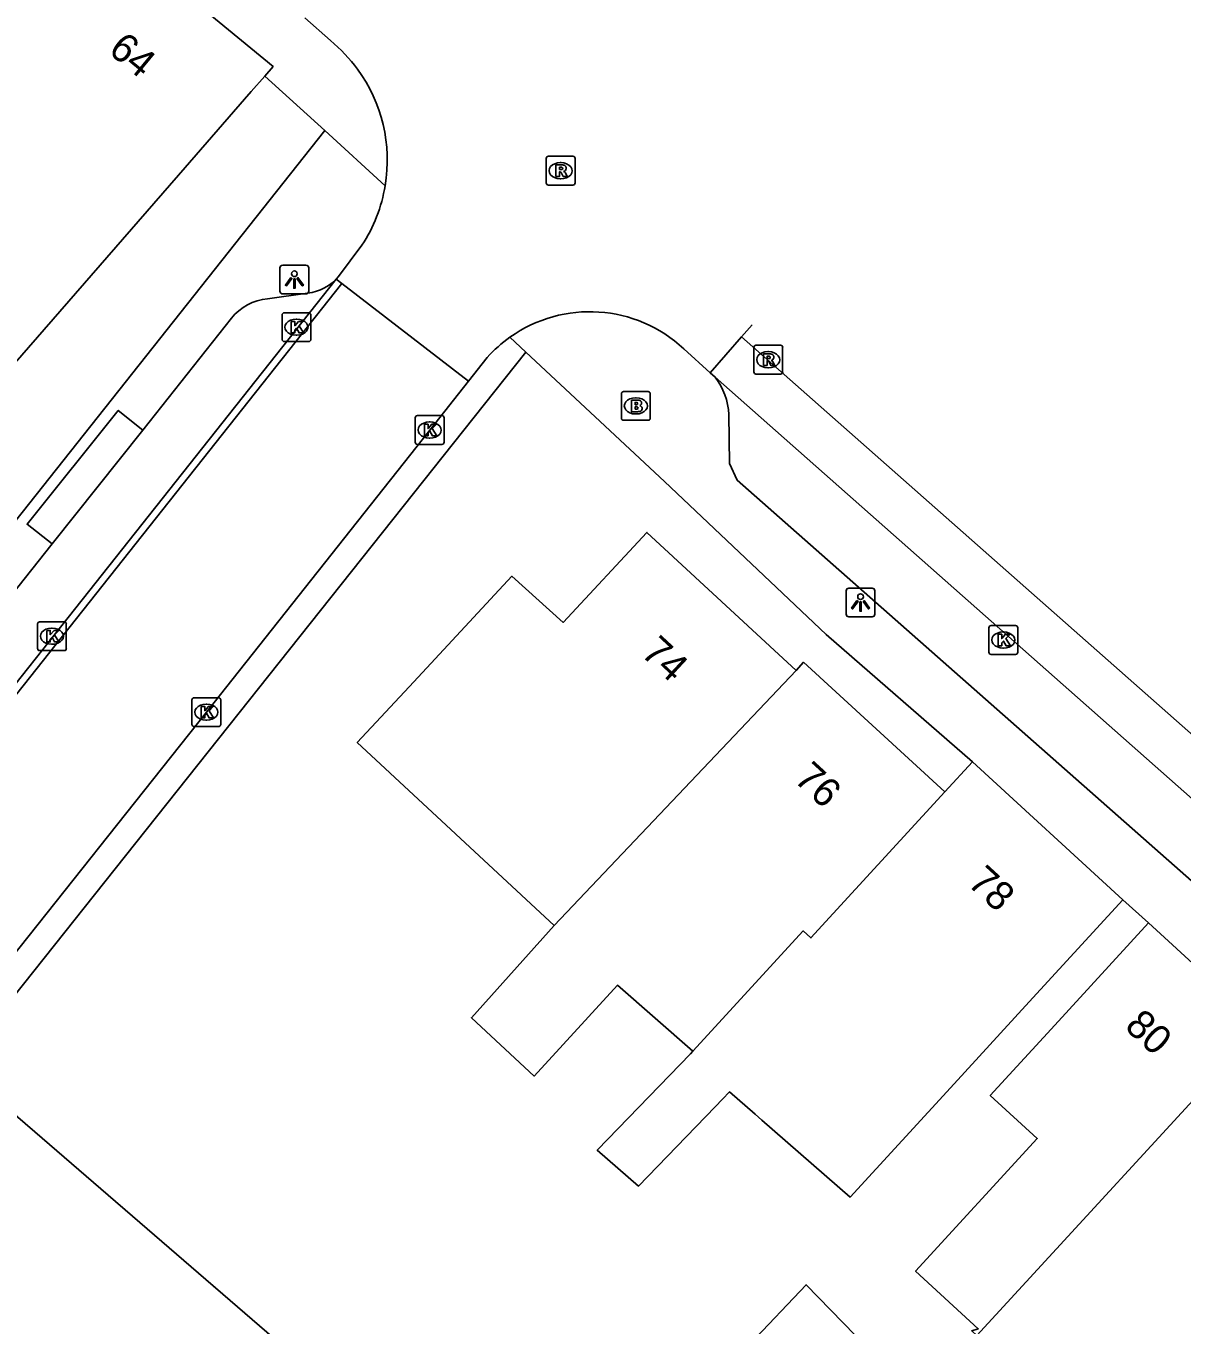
# Model space of a CAD drawing. Extents: x 161882 to 162509, y 381687 to 382379.
# Drawn here: x 162098.84 to 162138.96, y 382136.14 to 382181.25 of the extents above; entities that cross this region are included whole.
import ezdxf

# ---------------------------------------------------------------- set-up
doc = ezdxf.new("R2010")
doc.units = 0
for name, color, linetype in [('IMGEO_Brandkraan', 7, 'Continuous'), ('IMGEO_Kolk', 7, 'Continuous'), ('IMGEO_Lichtpunt', 7, 'Continuous'), ('IMGEO_Pand', 7, 'Continuous'), ('IMGEO_Pand_nummerreeks', 7, 'Continuous'), ('IMGEO_Rijbaan_lokaal_gesloten', 7, 'Continuous'), ('IMGEO_Rijbaan_lokaal_open', 7, 'Continuous'), ('IMGEO_Rioolput', 7, 'Continuous'), ('IMGEO_Voetpad_gesloten', 7, 'Continuous'), ('IMGEO_Voetpad_open', 7, 'Continuous')]:
    doc.layers.add(name, color=color, linetype=linetype)

msp = doc.modelspace()

# ---------------------------------------------------------------- linework, layer by layer
at = {"layer": 'IMGEO_Brandkraan'}
for p, q in [((162119.509, 382167.63), (162119.509, 382168.482)), ((162119.584, 382168.556), (162120.436, 382168.556)), ((162119.997, 382168.336), (162120.022, 382168.336)), ((162120.51, 382168.482), (162120.51, 382167.63)), ((162120.436, 382167.556), (162119.584, 382167.556)), ((162120.02, 382167.776), (162119.995, 382167.776))]:
    msp.add_line(p, q, dxfattribs=at)
for points in [[(162119.509, 382167.63), (162119.509, 382168.482)], [(162119.584, 382168.556), (162120.436, 382168.556)], [(162120.51, 382168.482), (162120.51, 382167.63)], [(162119.857, 382168.256), (162119.857, 382167.856), (162120.07, 382167.856)], [(162120.088, 382168.256), (162119.857, 382168.256)], [(162120.036, 382168.175), (162119.982, 382168.175), (162119.982, 382168.099)], [(162119.982, 382168.099), (162120.035, 382168.099)], [(162120.044, 382168.023), (162119.982, 382168.023), (162119.982, 382167.942)], [(162119.982, 382167.942), (162120.044, 382167.942)], [(162120.436, 382167.556), (162119.584, 382167.556)]]:
    msp.add_lwpolyline(points, dxfattribs=at)
for centre, radius, start, end in [((162119.586, 382168.48), 0.0765, 91.552, 178.448), ((162119.586, 382168.48), 0.0765, 91.552, 178.448), ((162120.434, 382168.48), 0.0765, 1.552, 88.448), ((162120.434, 382168.48), 0.0765, 1.552, 88.448), ((162120.037, 382168.137), 0.0379, 267.8285, 90.9355), ((162120.045, 382167.982), 0.0404, 269.8759, 90.5077), ((162120.076, 382168.107), 0.251, 268.6676, 293.5347), ((162120.092, 382168.111), 0.145, 59.4692, 91.5367), ((162120.117, 382168.158), 0.0922, 285.5137, 58.1501), ((162120.122, 382167.966), 0.105, 301.3115, 78.989), ((162119.586, 382167.632), 0.0765, 181.552, 268.448), ((162119.586, 382167.632), 0.0765, 181.552, 268.448), ((162120.434, 382167.632), 0.0765, 271.552, 358.448), ((162120.434, 382167.632), 0.0765, 271.552, 358.448)]:
    msp.add_arc(centre, radius, start, end, dxfattribs=at)
for centre, major_axis, ratio, start_param, end_param in [((162119.996, 382168.056), (-0.387, 0.002), 0.722429, 4.712389, 7.853982), ((162120.021, 382168.056), (-0.39, 0.002), 0.717154, 1.570796, 4.712389)]:
    msp.add_ellipse(centre, major_axis=major_axis, ratio=ratio, start_param=start_param, end_param=end_param, dxfattribs=at)
at = {"layer": 'IMGEO_Kolk'}
for p, q in [((162107.729, 382170.365), (162107.729, 382171.217)), ((162107.804, 382171.291), (162108.656, 382171.291)), ((162108.217, 382171.071), (162108.242, 382171.071)), ((162108.73, 382171.217), (162108.73, 382170.365)), ((162108.656, 382170.291), (162107.804, 382170.291)), ((162108.24, 382170.511), (162108.215, 382170.511)), ((162112.353, 382166.793), (162112.353, 382167.645)), ((162112.428, 382167.719), (162113.28, 382167.719)), ((162112.841, 382167.499), (162112.866, 382167.499)), ((162113.354, 382167.645), (162113.354, 382166.793)), ((162112.864, 382166.939), (162112.839, 382166.939)), ((162113.28, 382166.719), (162112.428, 382166.719)), ((162099.242, 382159.632), (162099.242, 382160.484)), ((162099.317, 382160.558), (162100.169, 382160.558)), ((162099.73, 382160.338), (162099.755, 382160.338)), ((162100.243, 382160.484), (162100.243, 382159.632)), ((162132.263, 382159.501), (162132.263, 382160.353)), ((162132.338, 382160.427), (162133.19, 382160.427)), ((162132.751, 382160.207), (162132.776, 382160.207)), ((162133.264, 382160.353), (162133.264, 382159.501)), ((162099.753, 382159.778), (162099.728, 382159.778)), ((162100.169, 382159.558), (162099.317, 382159.558)), ((162133.19, 382159.427), (162132.338, 382159.427)), ((162132.774, 382159.647), (162132.749, 382159.647)), ((162104.678, 382157.923), (162105.53, 382157.923)), ((162104.603, 382156.997), (162104.603, 382157.849)), ((162105.091, 382157.703), (162105.116, 382157.703)), ((162105.604, 382157.849), (162105.604, 382156.997)), ((162105.114, 382157.143), (162105.089, 382157.143)), ((162105.53, 382156.923), (162104.678, 382156.923))]:
    msp.add_line(p, q, dxfattribs=at)
for points in [[(162107.729, 382170.365), (162107.729, 382171.217)], [(162107.804, 382171.291), (162108.656, 382171.291)], [(162108.05, 382170.991), (162108.173, 382170.991), (162108.173, 382170.84), (162108.303, 382170.991), (162108.467, 382170.991), (162108.321, 382170.84), (162108.474, 382170.591), (162108.322, 382170.591), (162108.237, 382170.755), (162108.173, 382170.688), (162108.173, 382170.591), (162108.05, 382170.591), (162108.05, 382170.991)], [(162108.73, 382171.217), (162108.73, 382170.365)], [(162108.656, 382170.291), (162107.804, 382170.291)], [(162112.353, 382166.793), (162112.353, 382167.645)], [(162112.428, 382167.719), (162113.28, 382167.719)], [(162112.674, 382167.419), (162112.797, 382167.419), (162112.797, 382167.268), (162112.927, 382167.419), (162113.091, 382167.419), (162112.945, 382167.268), (162113.098, 382167.019), (162112.946, 382167.019), (162112.861, 382167.183), (162112.797, 382167.116), (162112.797, 382167.019), (162112.674, 382167.019), (162112.674, 382167.419)], [(162113.354, 382167.645), (162113.354, 382166.793)], [(162113.28, 382166.719), (162112.428, 382166.719)], [(162099.242, 382159.632), (162099.242, 382160.484)], [(162099.317, 382160.558), (162100.169, 382160.558)], [(162099.563, 382160.258), (162099.686, 382160.258), (162099.686, 382160.107), (162099.816, 382160.258), (162099.98, 382160.258), (162099.834, 382160.107), (162099.987, 382159.858), (162099.835, 382159.858), (162099.75, 382160.022), (162099.686, 382159.955), (162099.686, 382159.858), (162099.563, 382159.858), (162099.563, 382160.258)], [(162100.243, 382160.484), (162100.243, 382159.632)], [(162132.263, 382159.501), (162132.263, 382160.353)], [(162132.338, 382160.427), (162133.19, 382160.427)], [(162133.264, 382160.353), (162133.264, 382159.501)], [(162132.584, 382160.127), (162132.707, 382160.127), (162132.707, 382159.976), (162132.837, 382160.127), (162133.001, 382160.127), (162132.855, 382159.976), (162133.008, 382159.727), (162132.856, 382159.727), (162132.771, 382159.891), (162132.707, 382159.824), (162132.707, 382159.727), (162132.584, 382159.727), (162132.584, 382160.127)], [(162100.169, 382159.558), (162099.317, 382159.558)], [(162133.19, 382159.427), (162132.338, 382159.427)], [(162104.678, 382157.923), (162105.53, 382157.923)], [(162104.603, 382156.997), (162104.603, 382157.849)], [(162104.924, 382157.623), (162105.047, 382157.623), (162105.047, 382157.472), (162105.177, 382157.623), (162105.341, 382157.623), (162105.195, 382157.472), (162105.348, 382157.223), (162105.196, 382157.223), (162105.111, 382157.387), (162105.047, 382157.32), (162105.047, 382157.223), (162104.924, 382157.223), (162104.924, 382157.623)], [(162105.604, 382157.849), (162105.604, 382156.997)], [(162105.53, 382156.923), (162104.678, 382156.923)]]:
    msp.add_lwpolyline(points, dxfattribs=at)
for centre, start, end in [((162107.806, 382171.215), 91.552, 178.448), ((162107.806, 382171.215), 91.552, 178.448), ((162108.654, 382171.215), 1.552, 88.448), ((162108.654, 382171.215), 1.552, 88.448), ((162107.806, 382170.367), 181.552, 268.448), ((162107.806, 382170.367), 181.552, 268.448), ((162108.654, 382170.367), 271.552, 358.448), ((162108.654, 382170.367), 271.552, 358.448), ((162112.43, 382167.643), 91.552, 178.448), ((162112.43, 382167.643), 91.552, 178.448), ((162113.278, 382167.643), 1.552, 88.448), ((162113.278, 382167.643), 1.552, 88.448), ((162112.43, 382166.795), 181.552, 268.448), ((162112.43, 382166.795), 181.552, 268.448), ((162113.278, 382166.795), 271.552, 358.448), ((162113.278, 382166.795), 271.552, 358.448), ((162099.319, 382160.482), 91.552, 178.448), ((162099.319, 382160.482), 91.552, 178.448), ((162100.167, 382160.482), 1.552, 88.448), ((162100.167, 382160.482), 1.552, 88.448), ((162132.34, 382160.351), 91.552, 178.448), ((162132.34, 382160.351), 91.552, 178.448), ((162133.188, 382160.351), 1.552, 88.448), ((162133.188, 382160.351), 1.552, 88.448), ((162099.319, 382159.634), 181.552, 268.448), ((162099.319, 382159.634), 181.552, 268.448), ((162100.167, 382159.634), 271.552, 358.448), ((162100.167, 382159.634), 271.552, 358.448), ((162132.34, 382159.503), 181.552, 268.448), ((162132.34, 382159.503), 181.552, 268.448), ((162133.188, 382159.503), 271.552, 358.448), ((162133.188, 382159.503), 271.552, 358.448), ((162104.68, 382157.847), 91.552, 178.448), ((162104.68, 382157.847), 91.552, 178.448), ((162105.528, 382157.847), 1.552, 88.448), ((162105.528, 382157.847), 1.552, 88.448), ((162104.68, 382156.999), 181.552, 268.448), ((162104.68, 382156.999), 181.552, 268.448), ((162105.528, 382156.999), 271.552, 358.448), ((162105.528, 382156.999), 271.552, 358.448)]:
    msp.add_arc(centre, 0.0765, start, end, dxfattribs=at)
for centre, major_axis, ratio, start_param, end_param in [((162108.216, 382170.791), (-0.387, 0.002), 0.722429, 4.712389, 7.853982), ((162108.241, 382170.791), (-0.39, 0.002), 0.717154, 1.570796, 4.712389), ((162112.84, 382167.219), (-0.387, 0.002), 0.722429, 4.712389, 7.853982), ((162112.865, 382167.219), (-0.39, 0.002), 0.717154, 1.570796, 4.712389), ((162099.729, 382160.058), (-0.387, 0.002), 0.722429, 4.712389, 7.853982), ((162099.754, 382160.058), (-0.39, 0.002), 0.717154, 1.570796, 4.712389), ((162132.75, 382159.927), (-0.387, 0.002), 0.722429, 4.712389, 7.853982), ((162132.775, 382159.927), (-0.39, 0.002), 0.717154, 1.570796, 4.712389), ((162105.09, 382157.423), (-0.387, 0.002), 0.722429, 4.712389, 7.853982), ((162105.115, 382157.423), (-0.39, 0.002), 0.717154, 1.570796, 4.712389)]:
    msp.add_ellipse(centre, major_axis=major_axis, ratio=ratio, start_param=start_param, end_param=end_param, dxfattribs=at)
at = {"layer": 'IMGEO_Lichtpunt'}
for p, q in [((162107.658, 382172.848), (162107.658, 382172.041)), ((162107.658, 382172.848), (162107.658, 382172.041)), ((162108.56, 382172.943), (162107.752, 382172.943)), ((162108.56, 382172.943), (162107.752, 382172.943)), ((162108.654, 382172.041), (162108.654, 382172.848)), ((162108.654, 382172.041), (162108.654, 382172.848)), ((162107.752, 382171.947), (162108.56, 382171.947)), ((162107.752, 382171.947), (162108.56, 382171.947)), ((162127.308, 382161.634), (162127.308, 382160.827)), ((162127.308, 382161.634), (162127.308, 382160.827)), ((162128.21, 382161.729), (162127.402, 382161.729)), ((162128.21, 382161.729), (162127.402, 382161.729)), ((162128.304, 382160.827), (162128.304, 382161.634)), ((162128.304, 382160.827), (162128.304, 382161.634)), ((162127.402, 382160.733), (162128.21, 382160.733)), ((162127.402, 382160.733), (162128.21, 382160.733))]:
    msp.add_line(p, q, dxfattribs=at)
for points in [[(162108.032, 382172.512), (162108.071, 382172.484), (162107.883, 382172.222), (162107.845, 382172.249), (162108.032, 382172.512)], [(162108.134, 382172.464), (162108.181, 382172.464), (162108.181, 382172.142), (162108.134, 382172.142), (162108.134, 382172.464)], [(162108.244, 382172.484), (162108.282, 382172.511), (162108.469, 382172.249), (162108.43, 382172.221), (162108.244, 382172.484)], [(162127.682, 382161.298), (162127.721, 382161.27), (162127.533, 382161.008), (162127.495, 382161.035), (162127.682, 382161.298)], [(162127.784, 382161.25), (162127.831, 382161.25), (162127.831, 382160.928), (162127.784, 382160.928), (162127.784, 382161.25)], [(162127.894, 382161.27), (162127.932, 382161.297), (162128.119, 382161.035), (162128.08, 382161.007), (162127.894, 382161.27)]]:
    msp.add_lwpolyline(points, dxfattribs=at)
for centre in [(162108.157, 382172.646), (162127.807, 382161.432)]:
    msp.add_circle(centre, 0.0994, dxfattribs=at)
for centre, start, end in [((162107.752, 382172.848), 90, 180), ((162107.752, 382172.848), 90, 180), ((162108.56, 382172.848), 0, 90), ((162108.56, 382172.848), 0, 90), ((162107.752, 382172.041), 180, 270), ((162107.752, 382172.041), 180, 270), ((162108.56, 382172.041), 270, 0), ((162108.56, 382172.041), 270, 360), ((162127.402, 382161.634), 90, 180), ((162127.402, 382161.634), 90, 180), ((162128.21, 382161.634), 0, 90), ((162128.21, 382161.634), 0, 90), ((162127.402, 382160.827), 180, 270), ((162127.402, 382160.827), 180, 270), ((162128.21, 382160.827), 270, 0), ((162128.21, 382160.827), 270, 360)]:
    msp.add_arc(centre, 0.0946, start, end, dxfattribs=at)
at = {"layer": 'IMGEO_Pand'}
for points in [[(162101.353, 382184.848), (162107.416, 382179.84), (162107.127, 382179.509)], [(162107.127, 382179.509), (162106.66, 382178.972), (162104.134, 382176.069), (162098.382, 382169.46), (162096.968, 382167.835), (162096.36, 382168.364), (162093.197, 382171.117), (162092.454, 382170.263), (162090.19, 382172.233), (162091.28, 382173.513)], [(162117.176, 382150.009), (162110.339, 382156.373), (162112.301, 382158.48), (162115.707, 382162.139), (162117.492, 382160.54), (162120.395, 382163.662), (162125.568, 382158.867)], [(162125.568, 382158.867), (162117.176, 382150.009)], [(162125.568, 382158.867), (162125.829, 382159.152), (162130.734, 382154.653)], [(162130.734, 382154.653), (162131.693, 382155.698)], [(162131.693, 382155.698), (162136.914, 382150.91)], [(162121.989, 382145.649), (162125.818, 382149.824), (162126.084, 382149.58), (162130.734, 382154.653)], [(162136.914, 382150.91), (162133.535, 382147.226), (162131.051, 382144.517), (162127.442, 382140.582), (162124.386, 382143.249), (162124.15, 382143.466), (162123.259, 382144.232), (162123.015, 382143.98), (162122.764, 382143.72), (162120.096, 382140.962), (162118.667, 382142.21), (162121.906, 382145.559), (162121.989, 382145.649)], [(162121.989, 382145.649), (162119.367, 382147.936), (162116.48, 382144.785), (162114.301, 382146.812), (162117.176, 382150.009)], [(162131.849, 382135.773), (162131.669, 382135.938), (162131.894, 382136.009), (162129.716, 382138.006), (162133.943, 382142.615), (162132.309, 382144.112), (162134.424, 382146.419), (162137.803, 382150.104)], [(162137.803, 382150.104), (162141.709, 382146.522)], [(162141.709, 382146.522), (162131.849, 382135.773)], [(162097.277, 382144.452), (162113.475, 382130.48)], [(162120.058, 382131.359), (162125.918, 382137.539), (162129.757, 382133.588), (162125.219, 382128.746)]]:
    msp.add_lwpolyline(points, dxfattribs=at)
at = {"layer": 'IMGEO_Rijbaan_lokaal_gesloten'}
for points in [[(162122.586, 382169.208), (162123.677, 382170.45)], [(162123.677, 382170.45), (162160.677, 382137.773), (162159.551, 382136.515)], [(162122.761, 382169.05), (162122.586, 382169.208)], [(162122.761, 382169.05), (162158.594, 382137.366)]]:
    msp.add_lwpolyline(points, dxfattribs=at)
at = {"layer": 'IMGEO_Rijbaan_lokaal_open'}
for points in [[(162108.526, 382181.527), (162109.411, 382180.74)], [(162110.5, 382173.633), (162109.685, 382172.548)], [(162088.481, 382145.784), (162109.609, 382172.452)], [(162109.685, 382172.548), (162109.609, 382172.452)], [(162109.609, 382172.452), (162109.799, 382172.306)], [(162109.799, 382172.306), (162085.823, 382142.027), (162085.823, 382142.026)], [(162109.799, 382172.306), (162114.197, 382168.912)], [(162124.046, 382170.871), (162123.677, 382170.45)], [(162114.197, 382168.912), (162114.854, 382169.74)], [(162121.671, 382170.036), (162122.586, 382169.208)], [(162114.197, 382168.912), (162112.854, 382167.219), (162105.104, 382157.423), (162097.375, 382147.693), (162096.592, 382146.719)]]:
    msp.add_lwpolyline(points, dxfattribs=at)
for centre, radius, start, end in [((162105.946, 382176.52), 5.46, 36.2481, 50.6042), ((162106.008, 382176.582), 5.374, 350.5848, 36.1109), ((162106.016, 382176.579), 5.365, 326.6994, 350.6074), ((162118.407, 382166.555), 4.772, 46.8426, 125.4359), ((162118.467, 382166.491), 4.859, 125.5799, 138.0391)]:
    msp.add_arc(centre, radius, start, end, dxfattribs=at)
at = {"layer": 'IMGEO_Rioolput'}
for p, q in [((162116.899, 382175.798), (162116.899, 382176.65)), ((162116.974, 382176.724), (162117.826, 382176.724)), ((162117.387, 382176.504), (162117.412, 382176.504)), ((162117.9, 382176.65), (162117.9, 382175.798)), ((162117.41, 382175.944), (162117.385, 382175.944)), ((162117.826, 382175.724), (162116.974, 382175.724)), ((162124.103, 382169.235), (162124.103, 382170.087)), ((162124.178, 382170.161), (162125.03, 382170.161)), ((162125.104, 382170.087), (162125.104, 382169.235)), ((162124.591, 382169.941), (162124.616, 382169.941)), ((162125.03, 382169.161), (162124.178, 382169.161)), ((162124.614, 382169.381), (162124.589, 382169.381))]:
    msp.add_line(p, q, dxfattribs=at)
for points in [[(162116.899, 382175.798), (162116.899, 382176.65)], [(162116.974, 382176.724), (162117.826, 382176.724)], [(162117.488, 382176.422), (162117.236, 382176.424), (162117.236, 382176.024)], [(162117.9, 382176.65), (162117.9, 382175.798)], [(162117.236, 382176.024), (162117.36, 382176.024), (162117.36, 382176.186), (162117.371, 382176.186)], [(162117.414, 382176.343), (162117.36, 382176.343), (162117.36, 382176.262)], [(162117.36, 382176.262), (162117.412, 382176.262)], [(162117.418, 382176.157), (162117.489, 382176.024), (162117.629, 382176.024), (162117.564, 382176.15)], [(162117.826, 382175.724), (162116.974, 382175.724)], [(162124.103, 382169.235), (162124.103, 382170.087)], [(162124.178, 382170.161), (162125.03, 382170.161)], [(162125.104, 382170.087), (162125.104, 382169.235)], [(162124.692, 382169.859), (162124.44, 382169.861), (162124.44, 382169.461)], [(162124.44, 382169.461), (162124.564, 382169.461), (162124.564, 382169.623), (162124.575, 382169.623)], [(162124.618, 382169.78), (162124.564, 382169.78), (162124.564, 382169.699)], [(162124.564, 382169.699), (162124.616, 382169.699)], [(162125.03, 382169.161), (162124.178, 382169.161)], [(162124.622, 382169.594), (162124.693, 382169.461), (162124.833, 382169.461), (162124.768, 382169.587)]]:
    msp.add_lwpolyline(points, dxfattribs=at)
for centre, radius, start, end in [((162116.976, 382176.648), 0.0765, 91.552, 178.448), ((162116.976, 382176.648), 0.0765, 91.552, 178.448), ((162117.487, 382176.312), 0.109, 350.3612, 89.416), ((162117.824, 382176.648), 0.0765, 1.552, 88.448), ((162117.824, 382176.648), 0.0765, 1.552, 88.448), ((162117.37, 382176.133), 0.0533, 26.0293, 88.6989), ((162117.396, 382176.451), 0.19, 274.7715, 282.9687), ((162117.42, 382176.247), 0.0964, 77.0061, 93.1865), ((162117.434, 382176.304), 0.0378, 276.6634, 79.6772), ((162117.485, 382176.312), 0.112, 277.5842, 350.9817), ((162117.469, 382176.097), 0.108, 29.5134, 73.7905), ((162116.976, 382175.8), 0.0765, 181.552, 268.448), ((162116.976, 382175.8), 0.0765, 181.552, 268.448), ((162117.824, 382175.8), 0.0765, 271.552, 358.448), ((162117.824, 382175.8), 0.0765, 271.552, 358.448), ((162124.18, 382170.085), 0.0765, 91.552, 178.448), ((162124.18, 382170.085), 0.0765, 91.552, 178.448), ((162125.028, 382170.085), 0.0765, 1.552, 88.448), ((162125.028, 382170.085), 0.0765, 1.552, 88.448), ((162124.574, 382169.57), 0.0533, 26.0293, 88.6989), ((162124.6, 382169.888), 0.19, 274.7715, 282.9687), ((162124.624, 382169.684), 0.0964, 77.0061, 93.1865), ((162124.638, 382169.741), 0.0378, 276.6634, 79.6772), ((162124.691, 382169.749), 0.109, 350.3612, 89.416), ((162124.689, 382169.749), 0.112, 277.5842, 350.9817), ((162124.673, 382169.534), 0.108, 29.5134, 73.7905), ((162124.18, 382169.237), 0.0765, 181.552, 268.448), ((162124.18, 382169.237), 0.0765, 181.552, 268.448), ((162125.028, 382169.237), 0.0765, 271.552, 358.448), ((162125.028, 382169.237), 0.0765, 271.552, 358.448)]:
    msp.add_arc(centre, radius, start, end, dxfattribs=at)
for centre, major_axis, ratio, start_param, end_param in [((162117.386, 382176.224), (-0.387, 0.002), 0.722429, 4.712389, 7.853982), ((162117.411, 382176.224), (-0.39, 0.002), 0.717154, 1.570796, 4.712389), ((162124.59, 382169.661), (-0.387, 0.002), 0.722429, 4.712389, 7.853982), ((162124.615, 382169.661), (-0.39, 0.002), 0.717154, 1.570796, 4.712389)]:
    msp.add_ellipse(centre, major_axis=major_axis, ratio=ratio, start_param=start_param, end_param=end_param, dxfattribs=at)
at = {"layer": 'IMGEO_Voetpad_gesloten'}
for points in [[(162099.752, 382163.264), (162098.879, 382163.945), (162102.044, 382167.902), (162102.903, 382167.21)], [(162102.903, 382167.21), (162099.752, 382163.264)]]:
    msp.add_lwpolyline(points, dxfattribs=at)
at = {"layer": 'IMGEO_Voetpad_open'}
for points in [[(162109.213, 382177.62), (162107.127, 382179.509)], [(162084.632, 382147.554), (162085.103, 382147.186), (162109.213, 382177.62)], [(162109.213, 382177.62), (162111.309, 382175.703)], [(162107.229, 382171.779), (162108.617, 382171.975)], [(162102.903, 382167.21), (162105.972, 382171.101)], [(162115.64, 382170.443), (162116.187, 382169.927)], [(162097.305, 382146.167), (162116.187, 382169.927)], [(162116.187, 382169.927), (162121.003, 382165.434), (162126.612, 382160.118), (162131.693, 382155.698)], [(162154.673, 382138.002), (162123.53, 382165.475), (162123.255, 382166.055), (162123.234, 382167.756)], [(162089.158, 382149.901), (162099.752, 382163.264)], [(162136.914, 382150.91), (162137.803, 382150.104)]]:
    msp.add_lwpolyline(points, dxfattribs=at)
for centre, radius, start, end in [((162108.464, 382173.541), 1.574, 275.567, 320.8617), ((162107.402, 382169.954), 1.833, 95.4142, 141.2688), ((162120.959, 382167.658), 2.277, 2.4707, 37.6873)]:
    msp.add_arc(centre, radius, start, end, dxfattribs=at)

# ---------------------------------------------------------------- texts
at = {"layer": 'IMGEO_Pand_nummerreeks'}
for s, rotation, p in [('64', 320.443, (162101.659, 382180.341)), ('74', 317.1714, (162120.146, 382159.421)), ('76', 317.4693, (162125.456, 382155.044)), ('78', 317.4751, (162131.48, 382151.444)), ('80', 317.4768, (162136.933, 382146.453))]:
    msp.add_text(s, height=1, rotation=rotation, dxfattribs=at).set_placement(p)

doc.saveas('drawing.dxf')
